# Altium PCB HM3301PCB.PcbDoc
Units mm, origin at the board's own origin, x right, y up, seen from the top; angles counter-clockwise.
Board outline 130 x 92.5 mm, 2 copper layers (Top Layer, Bottom Layer); 0 components, 0 nets, 96 pads, 0 vias.
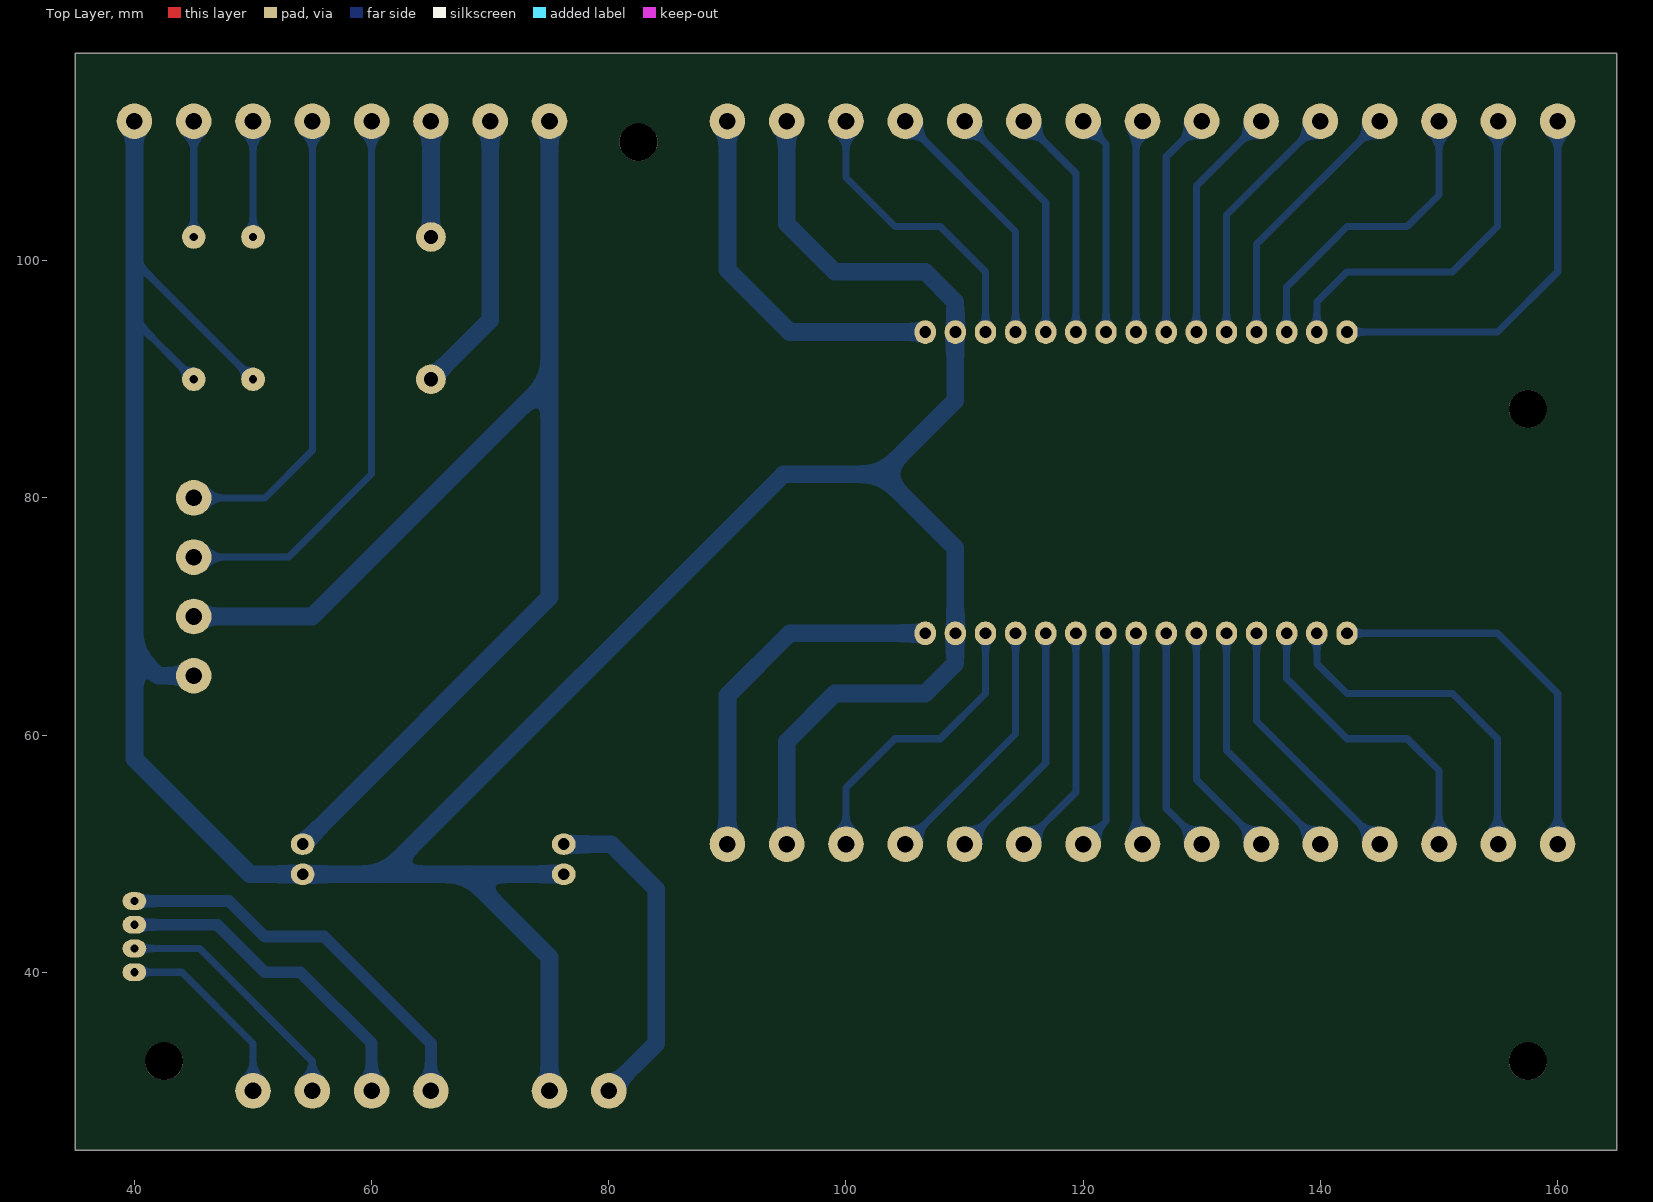
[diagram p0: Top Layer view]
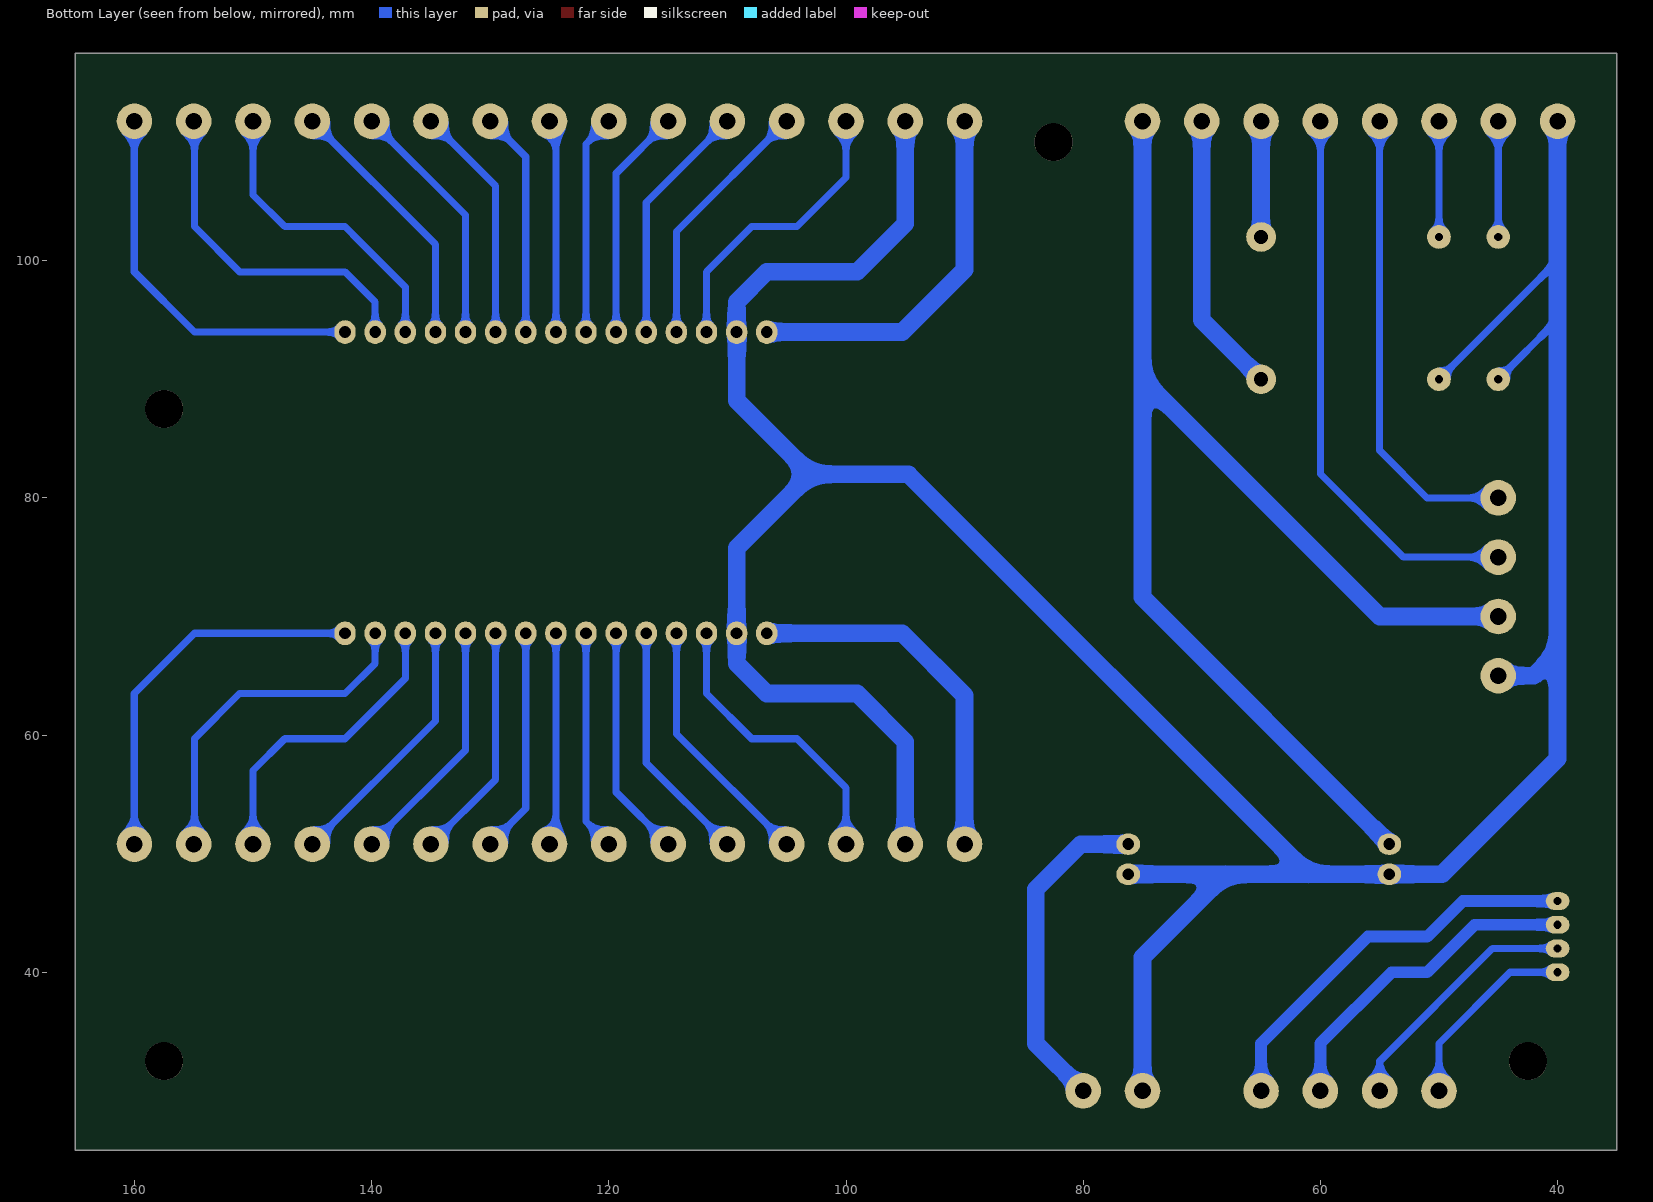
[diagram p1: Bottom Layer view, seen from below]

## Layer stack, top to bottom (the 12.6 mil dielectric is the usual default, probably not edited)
Top Solder: solder mask 0.0102, Solder Resist, Dk 3.5
Top Layer: signal copper 0.0356
Dielectric 1: dielectric 0.32, FR-4, Dk 4.8
Bottom Layer: signal copper 0.0356
Bottom Solder: solder mask 0.0102, Solder Resist, Dk 3.5

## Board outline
35,25 35,117.5 165,117.5 165,25

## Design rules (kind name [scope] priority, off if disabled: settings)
Clearance [All] p1: gap=0.254 ignorepadtopadclearanceinfootprint=FALSE
PolygonConnect [All] p1: connectstyle=Relief reliefconductorwidth=0.254 reliefentries=4 polygonreliefangle="90 Angle" airgapwidth=0.254
RoutingVias [All] p1: holewidth=0.711 width=1.27 viastyle="Through Hole" minholewidth=0.711 minwidth=1.27 maxholewidth=0.711 maxwidth=1.27
SolderMaskExpansion [All] p1: expansion=0 istentingtop=FALSE
Width [All] p1: maxlimit=5 minlimit=0.254 preferedwidth=0.3 toplayer_maxwidth=0.254 toplayer_prefwidth=0.254 minimp=50.000000 maximp=50.000000 favimp=50.000000
30 further rules are at their usual default settings.

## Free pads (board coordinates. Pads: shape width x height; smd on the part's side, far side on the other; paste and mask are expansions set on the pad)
  round 3 hole 1.4: 192(160,111.76) 193(155,111.76) 194(150,111.76) 195(145,111.76) 196(140,111.76) 197(135,111.76) 198(130,111.76) 199(125,111.76) 200(120,111.76) 201(115,111.76) 202(110,111.76) 203(105,111.76) 204(100,111.76) 205(95,111.76) 206(90,111.76) 239(140,50.8) 240(145,50.8) 241(150,50.8) 242(155,50.8) 243(160,50.8) 244(135,50.8) 245(130,50.8) 246(125,50.8) 247(120,50.8) 248(115,50.8) 249(110,50.8) 250(105,50.8) 251(100,50.8) 252(95,50.8) 253(90,50.8) 255(75,111.76) 256(70,111.76) 258(55,111.76) 259(50,111.76) 260(45,111.76) 261(40,111.76) 264(80,30) 265(75,30) 269(45,65) 270(45,80) 296(65,30) 297(60,30) 298(55,30) 299(50,30) 300(45,75) 301(45,70) 302(60,111.76) 303(65,111.76)
  oval 1.8x2 hole 1: 208(124.46,93.98) 209(127,93.98) 210(129.54,93.98) 211(132.08,93.98) 212(134.62,93.98) 213(137.16,93.98) 214(139.7,93.98) 215(142.24,93.98) 216(121.92,93.98) 217(119.38,93.98) 218(116.84,93.98) 219(114.3,93.98) 220(111.76,93.98) 221(109.22,93.98) 222(106.68,93.98) 223(142.24,68.58) 224(139.7,68.58) 225(137.16,68.58) 226(134.62,68.58) 227(132.08,68.58) 228(129.54,68.58) 229(127,68.58) 230(124.46,68.58) 231(121.92,68.58) 232(119.38,68.58) 233(116.84,68.58) 234(114.3,68.58) 235(111.76,68.58) 236(109.22,68.58) 237(106.68,68.58)
  oval 2x1.8 hole 1: 285(76.2,50.8) 286(76.2,48.26) 316(54.186,50.8) 317(54.186,48.26)
  oval 2x1.5 hole 0.7: 320(40,46) 321(40,44) 322(40,42) 323(40,40)
  round 2.5 hole 1.2: 329(65,102) 330(65,90)
  round 2 hole 0.7: 332(45,102) 333(45,90) 334(50,102) 335(50,90)
  round 3.2 hole 3.2: ""(42.5,32.5) ""(82.5,110) ""(157.5,32.5) ""(157.5,87.5)

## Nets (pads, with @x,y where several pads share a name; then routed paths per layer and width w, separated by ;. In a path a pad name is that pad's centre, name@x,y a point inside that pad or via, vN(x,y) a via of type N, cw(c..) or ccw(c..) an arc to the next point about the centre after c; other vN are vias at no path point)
copper on no net: | length 1314.3
  Bottom Layer w0.3: 40,100 40,101.6
  Bottom Layer w0.6: 40,40 44,40 50,34 50,30 ; 40,42 45.5,42 55,32.5 55,30 ; 40,95 45,90 ; 40,100 50,90 ; 45,75 53,75 60,82 60,111.76 ; 45,80 51,80 55,84 55,111.76 ; 45,102 45,111.76 ; 50,102 50,111.76 ; 100,50.8 100,55.55 104.14,59.69 107.95,59.69 111.76,63.5 111.76,68.58 ; 100,111.76 100,107.01 104.14,102.87 107.95,102.87 111.76,99.06 111.76,93.98 ; 105,50.8 114.3,60.1 114.3,68.58 ; 105,111.76 114.3,102.46 114.3,93.98 ; 110,50.8 116.84,57.64 116.84,68.58 ; 110,111.76 116.84,104.92 116.84,93.98 ; 115,50.8 119.38,55.18 119.38,68.58 ; 115,111.76 119.38,107.38 119.38,93.98 ; 120,50.8 121.92,52.72 121.92,68.58 ; 120,111.76 121.92,109.84 121.92,93.98 ; 124.46,68.58 124.46,51.34 125,50.8 124.541,51.259 ; 124.46,93.98 124.46,111.22 125,111.76 ; 127,68.58 127,53.8 130,50.8 ; 127,93.98 127,108.76 130,111.76 ; 129.54,68.58 129.54,56.26 135,50.8 ; 129.54,93.98 129.54,106.3 135,111.76 ; 132.08,68.58 132.08,58.72 140,50.8 ; 132.08,93.98 132.08,103.84 140,111.76 ; 134.62,68.58 134.62,61.18 145,50.8 ; 134.62,93.98 134.62,101.38 145,111.76 ; 137.16,68.58 137.16,64.77 142.24,59.69 147.32,59.69 150,57.01 150,50.8 ; 137.16,93.98 137.16,97.79 140.97,101.6 142.24,102.87 147.32,102.87 150,105.55 150,111.76 ; 139.7,68.58 139.7,66.04 142.24,63.5 151.13,63.5 154.94,59.69 154.94,50.8 ; 139.7,93.98 139.7,96.52 142.24,99.06 151.13,99.06 154.94,102.87 154.94,111.76 ; 142.24,68.58 154.94,68.58 160.02,63.5 160.02,50.8 ; 142.24,93.98 154.94,93.98 160.02,99.06 160.02,111.76
  Bottom Layer w1: 40,44 47,44 51,40 54,40 60,34 60,30 ; 40,46 48,46 51,43 56,43 65,34 65,30 ; 44.809,90.191 45,90
  Bottom Layer w1.5: 40,68 40,58 49.74,48.26 54.186,48.26 61,48.26 ; 40,111.76 40,67 42,65 45,65 ; 45,70 55,70 75,90 ; 54.186,50.8 75,71.614 75,90 ; 65,90 70,95 70,111.76 ; 65,102 65,111.76 ; 75,30 75,41.26 68,48.26 ; 75,111.76 75,90 ; 76.2,48.26 68,48.26 ; 76.2,50.8 80.2,50.8 84,47 84,34 80,30 ; 90,50.8 90,63.33 95.25,68.58 106.68,68.58 ; 90,111.76 90,99.23 95.25,93.98 106.68,93.98 ; 95,50.8 95,59.44 99.06,63.5 106.68,63.5 109.22,66.04 109.22,68.58 109.22,75.78 103,82 ; 95,111.76 95,103.12 99.06,99.06 106.68,99.06 109.22,96.52 109.22,93.98 109.22,88.22 103,82 ; 61,48.26 68,48.26 ; 61,48.26 94.74,82 103,82

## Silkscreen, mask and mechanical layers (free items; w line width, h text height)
Mechanical 1:
  the board outline again, w0.254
